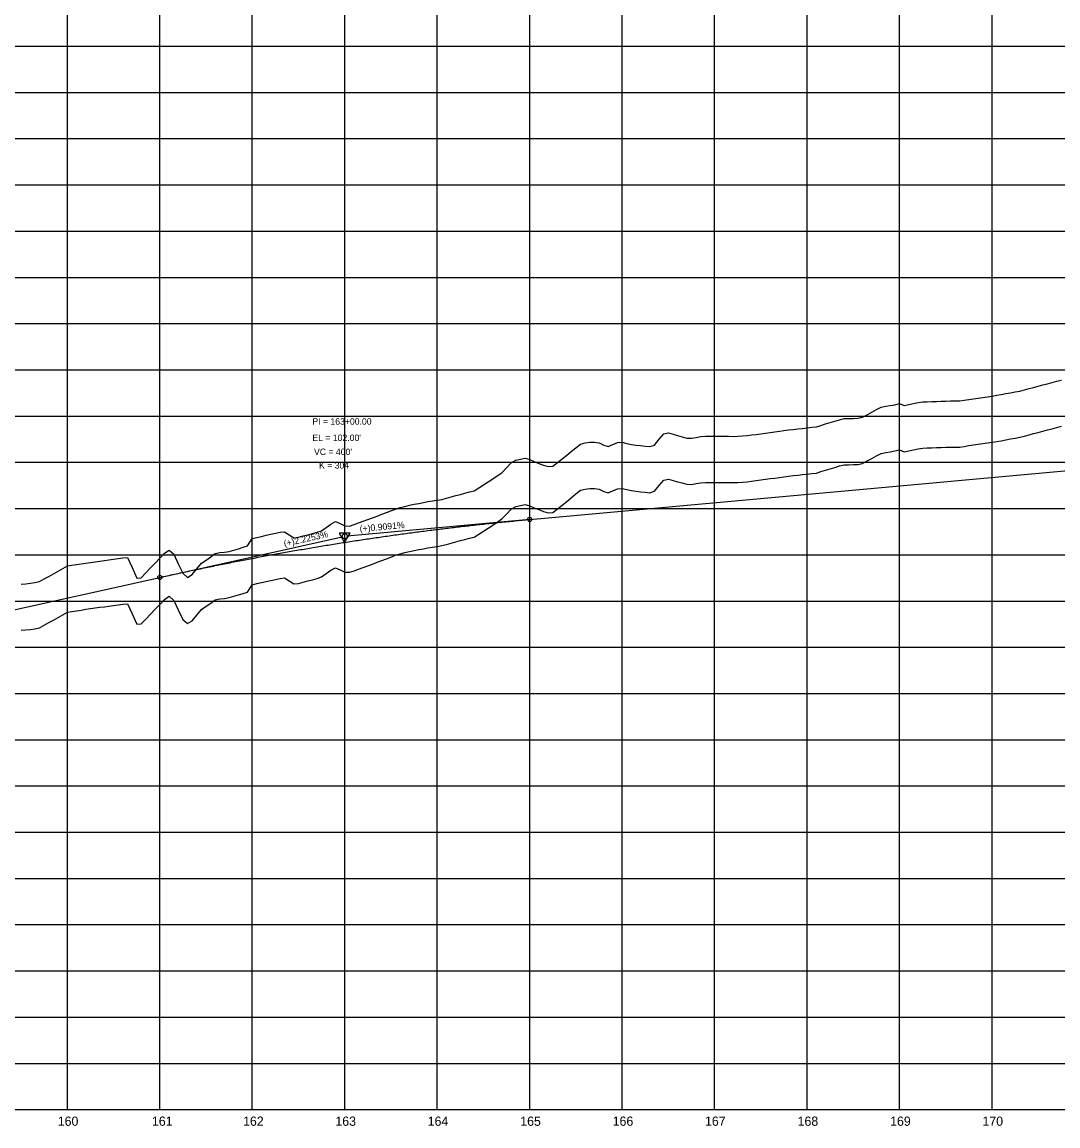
# Model space of a CAD drawing. Extents: x 2345490 to 2445302, y 465165 to 573888.
# Drawn here: x 2396273 to 2397393, y 564259 to 565453 of the extents above; entities that cross this region are included whole.
import ezdxf

# ---------------------------------------------------------------- set-up
doc = ezdxf.new("R2010")
doc.units = 0
for name, color, linetype in [('Old_Level_1', 7, 'Continuous'), ('Old_Level_2', 7, 'Continuous'), ('Old_Level_57', 7, 'Continuous'), ('Old_Level_62', 7, 'Continuous'), ('Old_Level_63', 7, 'Continuous')]:
    doc.layers.add(name, color=color, linetype=linetype)

msp = doc.modelspace()

# ---------------------------------------------------------------- linework, layer by layer
at = {"layer": 'Old_Level_1'}
for points in [[(2396871.5425, 564942.274), (2396876.5425, 564946.27125), (2396881.5425, 564947.5325), (2396886.5425, 564948.36975), (2396891.5425, 564948.22425), (2396896.5425, 564947.4575), (2396901.5425, 564944.9875), (2396906.5425, 564943.62775), (2396911.5425, 564945.76425), (2396916.5425, 564947.90375), (2396921.5425, 564948.2005), (2396926.5425, 564947.03125), (2396931.5425, 564945.8665), (2396936.5425, 564945.148), (2396941.5425, 564944.604), (2396946.5425, 564944.06375), (2396951.5425, 564943.52725), (2396956.5425, 564945.192), (2396961.5425, 564951.4745), (2396966.5425, 564957.15275), (2396971.5425, 564958.329), (2396976.5425, 564956.93625), (2396981.5425, 564955.54675), (2396986.5425, 564954.16075), (2396991.5425, 564952.77775), (2396996.5425, 564952.68825), (2397001.5425, 564953.484), (2397006.5425, 564954.28125), (2397011.5425, 564954.82525), (2397016.5425, 564954.83175), (2397021.5425, 564954.8395), (2397026.5425, 564954.84875), (2397031.5425, 564954.85925), (2397036.5425, 564954.80125), (2397041.5425, 564954.53975), (2397046.5425, 564954.86125), (2397051.5425, 564955.185), (2397056.5425, 564955.5105), (2397061.5425, 564956.0615), (2397066.5425, 564956.75125), (2397071.5425, 564957.4425), (2397076.5425, 564958.13575), (2397081.5425, 564958.83075), (2397086.5425, 564959.5275), (2397091.5425, 564960.22625), (2397096.5425, 564960.92675), (2397101.5425, 564961.62875), (2397106.5425, 564962.112), (2397111.5425, 564962.63875), (2397116.5425, 564963.2095), (2397121.5425, 564963.781), (2397126.5425, 564964.3535), (2397131.5425, 564964.93475), (2397136.5425, 564966.451), (2397141.5425, 564967.96875), (2397146.5425, 564969.488), (2397151.5425, 564971.009), (2397156.5425, 564972.53125), (2397161.5425, 564973.857), (2397166.5425, 564973.9555), (2397171.5425, 564974.06), (2397176.5425, 564974.16475), (2397181.5425, 564975.24425), (2397186.5425, 564977.9885), (2397191.5425, 564980.734), (2397196.5425, 564983.45175), (2397201.5425, 564986.16275), (2397206.5425, 564987.2385), (2397211.5425, 564988.02), (2397216.5425, 564988.80225), (2397221.5425, 564989.99125), (2397226.5425, 564987.83175), (2397231.5425, 564989.0185), (2397236.5425, 564990.06275), (2397241.5425, 564991.1085), (2397246.5425, 564991.86325), (2397251.5425, 564992.035), (2397256.5425, 564992.20725), (2397261.5425, 564992.3805), (2397266.5425, 564992.5545), (2397271.5425, 564992.729), (2397276.5425, 564992.84325), (2397281.5425, 564992.82825), (2397286.5425, 564993.04425), (2397291.5425, 564993.781), (2397296.5425, 564994.5185), (2397301.5425, 564995.25675), (2397306.5425, 564995.996), (2397311.5425, 564996.736), (2397316.5425, 564997.47675), (2397321.5425, 564998.21825), (2397326.5425, 564998.96075), (2397331.5425, 564999.87975), (2397336.5425, 565000.85575), (2397341.5425, 565001.79475), (2397346.5425, 565002.645), (2397351.5425, 565003.5365), (2397356.5425, 565004.8705), (2397361.5425, 565006.205), (2397366.5425, 565007.5405), (2397371.5425, 565008.8765)], [(2397371.5425, 565008.8765), (2397376.5425, 565010.2135), (2397381.5425, 565011.551), (2397386.5425, 565012.8895), (2397391.5425, 565014.2285), (2397396.5425, 565015.50025)], [(2396371.5425, 564821.8075), (2396376.5425, 564822.51275), (2396381.5425, 564823.21975), (2396386.5425, 564823.41025), (2396391.5425, 564812.7395), (2396396.5425, 564801.323), (2396401.5425, 564801.66625), (2396406.5425, 564806.9515), (2396411.5425, 564812.239), (2396416.5425, 564817.529), (2396421.5425, 564822.8215), (2396426.5425, 564828.11625), (2396431.5425, 564831.665), (2396436.5425, 564827.17725), (2396441.5425, 564816.8385), (2396446.5425, 564806.5055), (2396451.5425, 564802.0505), (2396456.5425, 564805.1195), (2396461.5425, 564811.28725), (2396466.5425, 564817.27225), (2396471.5425, 564820.7955), (2396476.5425, 564824.321), (2396481.5425, 564827.8485), (2396486.5425, 564828.9995), (2396491.5425, 564829.1725), (2396496.5425, 564830.183), (2396501.5425, 564831.64825), (2396506.5425, 564833.1215), (2396511.5425, 564834.60325), (2396516.5425, 564836.09325), (2396521.5425, 564844.14225), (2396526.5425, 564845.28575), (2396531.5425, 564846.429), (2396536.5425, 564847.5725), (2396541.5425, 564848.71625), (2396546.5425, 564849.85975), (2396551.5425, 564851.0035), (2396556.5425, 564851.4305), (2396561.5425, 564848.2085), (2396566.5425, 564844.995), (2396571.5425, 564845.5455), (2396576.5425, 564846.8515), (2396581.5425, 564848.16775), (2396586.5425, 564849.49425), (2396591.5425, 564850.8315), (2396596.5425, 564852.5395), (2396601.5425, 564856.1645), (2396606.5425, 564859.79125), (2396611.5425, 564862.40575), (2396616.5425, 564860.2005), (2396621.5425, 564857.8605), (2396626.5425, 564857.544), (2396631.5425, 564859.275), (2396636.5425, 564861.008), (2396641.5425, 564862.7425), (2396646.5425, 564864.60325), (2396651.5425, 564866.4955), (2396656.5425, 564868.38775), (2396661.5425, 564870.28), (2396666.5425, 564872.172), (2396671.5425, 564874.06425), (2396676.5425, 564875.95625), (2396681.5425, 564877.518), (2396686.5425, 564878.8225), (2396691.5425, 564880.0945), (2396696.5425, 564881.08325), (2396701.5425, 564882.071), (2396706.5425, 564883.05825), (2396711.5425, 564883.97175), (2396716.5425, 564884.78325), (2396721.5425, 564885.594), (2396726.5425, 564886.404), (2396731.5425, 564887.79625), (2396736.5425, 564889.23125), (2396741.5425, 564890.5355), (2396746.5425, 564891.838), (2396751.5425, 564893.13925), (2396756.5425, 564894.43875), (2396761.5425, 564895.737), (2396766.5425, 564898.93675), (2396771.5425, 564902.16525), (2396776.5425, 564905.4015), (2396781.5425, 564908.64525), (2396786.5425, 564911.89625), (2396791.5425, 564915.28525), (2396796.5425, 564920.54075), (2396801.5425, 564925.80425), (2396806.5425, 564928.726), (2396811.5425, 564929.896), (2396816.5425, 564931.039), (2396821.5425, 564929.57075), (2396826.5425, 564927.4465), (2396831.5425, 564925.3235), (2396836.5425, 564923.324), (2396841.5425, 564921.83175), (2396846.5425, 564922.3), (2396851.5425, 564926.29325), (2396856.5425, 564930.28725), (2396861.5425, 564934.282), (2396866.5425, 564938.2775), (2396871.5425, 564942.274)], [(2396271.5425, 564794.8795), (2396276.5425, 564795.2105), (2396281.5425, 564795.8615), (2396286.5425, 564796.5125), (2396291.5425, 564797.64525), (2396296.5425, 564800.418), (2396301.5425, 564803.191), (2396306.5425, 564805.9645), (2396311.5425, 564808.73825), (2396316.5425, 564811.5125), (2396321.5425, 564814.4905), (2396326.5425, 564815.312), (2396331.5425, 564816.05), (2396336.5425, 564816.7895), (2396341.5425, 564817.53), (2396346.5425, 564818.272), (2396351.5425, 564819.003), (2396356.5425, 564819.7015), (2396361.5425, 564820.402), (2396366.5425, 564821.10375), (2396371.5425, 564821.8075)]]:
    msp.add_lwpolyline(points, dxfattribs=at)
at = {"layer": 'Old_Level_2'}
for p, q in [((2396821.5425, 564914.71575), (2398621.5425, 565078.352)), ((2396821.5425, 564914.71575), (2396624.28125, 564896.78275)), ((2396421.5425, 564852.02725), (2396618.85825, 564895.9365)), ((2396221.5425, 564807.5205), (2396421.5425, 564852.02725))]:
    msp.add_line(p, q, dxfattribs=at)
msp.add_lwpolyline([(2396627.299, 564899.86625), (2396615.5565, 564899.85175), (2396621.44, 564889.7335)], close=True, dxfattribs=at)
for centre, radius in [((2396821.5425, 564914.71575), 2.25), ((2396621.5425, 564896.534), 2.75), ((2396421.5425, 564852.02725), 2.25)]:
    msp.add_circle(centre, radius, dxfattribs=at)
msp.add_spline([(2396421.5425, 564852.02725), (2396429.5425, 564853.797), (2396437.5425, 564855.5455), (2396445.5425, 564857.27325), (2396453.5425, 564858.97975), (2396461.5425, 564860.66525), (2396469.5425, 564862.32975), (2396477.5425, 564863.973), (2396485.5425, 564865.5955), (2396493.5425, 564867.19675), (2396501.5425, 564868.777), (2396509.5425, 564870.336), (2396517.5425, 564871.874), (2396525.5425, 564873.391), (2396533.5425, 564874.887), (2396541.5425, 564876.362), (2396549.5425, 564877.81575), (2396557.5425, 564879.2485), (2396565.5425, 564880.66025), (2396573.5425, 564882.051), (2396581.5425, 564883.4205), (2396589.5425, 564884.769), (2396597.5425, 564886.0965), (2396605.5425, 564887.403), (2396613.5425, 564888.68825), (2396621.5425, 564889.95275), (2396629.5425, 564891.196), (2396637.5425, 564892.418), (2396645.5425, 564893.61925), (2396653.5425, 564894.79925), (2396661.5425, 564895.95825), (2396669.5425, 564897.09625), (2396677.5425, 564898.213), (2396685.5425, 564899.309), (2396693.5425, 564900.38375), (2396701.5425, 564901.43725), (2396709.5425, 564902.47), (2396717.5425, 564903.4815), (2396725.5425, 564904.472), (2396733.5425, 564905.4415), (2396741.5425, 564906.39), (2396749.5425, 564907.31725), (2396757.5425, 564908.2235), (2396765.5425, 564909.10875), (2396773.5425, 564909.973), (2396781.5425, 564910.816), (2396789.5425, 564911.638), (2396797.5425, 564912.439), (2396805.5425, 564913.219), (2396813.5425, 564913.978), (2396821.5425, 564914.71575)], degree=3, dxfattribs=at)
at = {"layer": 'Old_Level_57'}
for p, q in [((2396321.5425, 564276.534), (2396321.5425, 566615.2835)), ((2396421.54225, 564276.534), (2396421.54225, 566615.2835)), ((2396521.54225, 564276.534), (2396521.54225, 566615.2835)), ((2396621.54225, 564276.534), (2396621.54225, 566615.2835)), ((2396721.54225, 564276.534), (2396721.54225, 566615.2835)), ((2396821.54225, 564276.534), (2396821.54225, 566615.2835)), ((2396921.54225, 564276.534), (2396921.54225, 566615.2835)), ((2397021.54225, 564276.534), (2397021.54225, 566615.2835)), ((2397121.54225, 564276.534), (2397121.54225, 566615.2835)), ((2397221.54225, 564276.534), (2397221.54225, 566615.2835)), ((2397321.5425, 564276.534), (2397321.5425, 566615.2835)), ((2381271.5425, 565426.534), (2410861.12275, 565426.534)), ((2381271.5425, 565376.534), (2410861.12275, 565376.534)), ((2381271.5425, 565326.534), (2410861.12275, 565326.534)), ((2381271.5425, 565276.534), (2410861.12275, 565276.534)), ((2381271.5425, 565226.534), (2410861.12275, 565226.534)), ((2381271.5425, 565176.534), (2410861.12275, 565176.534)), ((2381271.5425, 565126.534), (2410861.12275, 565126.534)), ((2381271.5425, 565076.534), (2410861.12275, 565076.534)), ((2381271.5425, 565026.534), (2410861.12275, 565026.534)), ((2381271.5425, 564976.534), (2410861.12275, 564976.534)), ((2381271.5425, 564926.534), (2410861.12275, 564926.534)), ((2381271.5425, 564876.534), (2410861.12275, 564876.534)), ((2381271.5425, 564826.534), (2410861.12275, 564826.534)), ((2381271.54275, 564776.534), (2410861.123, 564776.534)), ((2381271.5425, 564726.534), (2410861.12275, 564726.534)), ((2381271.54275, 564676.534), (2410861.123, 564676.534)), ((2381271.5425, 564626.534), (2410861.12275, 564626.534)), ((2381271.54275, 564576.534), (2410861.123, 564576.534)), ((2381271.5425, 564526.534), (2410861.12275, 564526.534)), ((2381271.54275, 564476.534), (2410861.123, 564476.534)), ((2381271.5425, 564426.534), (2410861.12275, 564426.534)), ((2381271.54275, 564376.534), (2410861.123, 564376.534)), ((2381271.5425, 564326.534), (2410861.12275, 564326.534)), ((2381271.54275, 564276.534), (2410861.123, 564276.534))]:
    msp.add_line(p, q, dxfattribs=at)
at = {"layer": 'Old_Level_63'}
msp.add_line((2381321.5425, 564276.534), (2406689.937, 564276.534), dxfattribs=at)
for points in [[(2396871.5425, 564992.27375), (2396876.5425, 564996.271), (2396881.5425, 564997.53225), (2396886.5425, 564998.3695), (2396891.5425, 564998.224), (2396896.5425, 564997.45725), (2396901.5425, 564994.98725), (2396906.5425, 564993.6275), (2396911.5425, 564995.764), (2396916.5425, 564997.9035), (2396921.5425, 564998.20025), (2396926.5425, 564997.031), (2396931.5425, 564995.86625), (2396936.5425, 564995.14775), (2396941.5425, 564994.60375), (2396946.5425, 564994.0635), (2396951.5425, 564993.527), (2396956.5425, 564995.19175), (2396961.5425, 565001.47425), (2396966.5425, 565007.1525), (2396971.5425, 565008.32875), (2396976.5425, 565006.936), (2396981.5425, 565005.5465), (2396986.5425, 565004.1605), (2396991.5425, 565002.7775), (2396996.5425, 565002.688), (2397001.5425, 565003.48375), (2397006.5425, 565004.281), (2397011.5425, 565004.825), (2397016.5425, 565004.8315), (2397021.5425, 565004.83925), (2397026.5425, 565004.8485), (2397031.5425, 565004.859), (2397036.5425, 565004.801), (2397041.5425, 565004.5395), (2397046.5425, 565004.861), (2397051.5425, 565005.18475), (2397056.5425, 565005.51025), (2397061.5425, 565006.06125), (2397066.5425, 565006.751), (2397071.5425, 565007.44225), (2397076.5425, 565008.1355), (2397081.5425, 565008.8305), (2397086.5425, 565009.52725), (2397091.5425, 565010.226), (2397096.5425, 565010.9265), (2397101.5425, 565011.6285), (2397106.5425, 565012.11175), (2397111.5425, 565012.6385), (2397116.5425, 565013.20925), (2397121.5425, 565013.78075), (2397126.5425, 565014.35325), (2397131.5425, 565014.9345), (2397136.5425, 565016.45075), (2397141.5425, 565017.9685), (2397146.5425, 565019.48775), (2397151.5425, 565021.00875), (2397156.5425, 565022.531), (2397161.5425, 565023.85675), (2397166.5425, 565023.95525), (2397171.5425, 565024.05975), (2397176.5425, 565024.1645), (2397181.5425, 565025.244), (2397186.5425, 565027.98825), (2397191.5425, 565030.73375), (2397196.5425, 565033.4515), (2397201.5425, 565036.1625), (2397206.5425, 565037.23825), (2397211.5425, 565038.01975), (2397216.5425, 565038.802), (2397221.5425, 565039.991), (2397226.5425, 565037.8315), (2397231.5425, 565039.01825), (2397236.5425, 565040.0625), (2397241.5425, 565041.10825), (2397246.5425, 565041.863), (2397251.5425, 565042.03475), (2397256.5425, 565042.207), (2397261.5425, 565042.38025), (2397266.5425, 565042.55425), (2397271.5425, 565042.72875), (2397276.5425, 565042.843), (2397281.5425, 565042.828), (2397286.5425, 565043.044), (2397291.5425, 565043.78075), (2397296.5425, 565044.51825), (2397301.5425, 565045.2565), (2397306.5425, 565045.99575), (2397311.5425, 565046.73575), (2397316.5425, 565047.4765), (2397321.5425, 565048.218), (2397326.5425, 565048.9605), (2397331.5425, 565049.8795), (2397336.5425, 565050.8555), (2397341.5425, 565051.7945), (2397346.5425, 565052.64475), (2397351.5425, 565053.53625), (2397356.5425, 565054.87025), (2397361.5425, 565056.20475), (2397366.5425, 565057.54025), (2397371.5425, 565058.87625)], [(2397371.5425, 565058.87625), (2397376.5425, 565060.21325), (2397381.5425, 565061.55075), (2397386.5425, 565062.88925), (2397391.5425, 565064.22825), (2397396.5425, 565065.5)], [(2396371.5425, 564871.80725), (2396376.5425, 564872.5125), (2396381.5425, 564873.2195), (2396386.5425, 564873.41), (2396391.5425, 564862.73925), (2396396.5425, 564851.32275), (2396401.5425, 564851.666), (2396406.5425, 564856.95125), (2396411.5425, 564862.23875), (2396416.5425, 564867.52875), (2396421.5425, 564872.82125), (2396426.5425, 564878.116), (2396431.5425, 564881.66475), (2396436.5425, 564877.177), (2396441.5425, 564866.83825), (2396446.5425, 564856.50525), (2396451.5425, 564852.05025), (2396456.5425, 564855.11925), (2396461.5425, 564861.287), (2396466.5425, 564867.272), (2396471.5425, 564870.79525), (2396476.5425, 564874.32075), (2396481.5425, 564877.84825), (2396486.5425, 564878.99925), (2396491.5425, 564879.17225), (2396496.5425, 564880.18275), (2396501.5425, 564881.648), (2396506.5425, 564883.12125), (2396511.5425, 564884.603), (2396516.5425, 564886.093), (2396521.5425, 564894.142), (2396526.5425, 564895.2855), (2396531.5425, 564896.42875), (2396536.5425, 564897.57225), (2396541.5425, 564898.716), (2396546.5425, 564899.8595), (2396551.5425, 564901.00325), (2396556.5425, 564901.43025), (2396561.5425, 564898.20825), (2396566.5425, 564894.99475), (2396571.5425, 564895.54525), (2396576.5425, 564896.85125), (2396581.5425, 564898.1675), (2396586.5425, 564899.494), (2396591.5425, 564900.83125), (2396596.5425, 564902.53925), (2396601.5425, 564906.16425), (2396606.5425, 564909.791), (2396611.5425, 564912.4055), (2396616.5425, 564910.20025), (2396621.5425, 564907.86025), (2396626.5425, 564907.54375), (2396631.5425, 564909.27475), (2396636.5425, 564911.00775), (2396641.5425, 564912.74225), (2396646.5425, 564914.603), (2396651.5425, 564916.49525), (2396656.5425, 564918.3875), (2396661.5425, 564920.27975), (2396666.5425, 564922.17175), (2396671.5425, 564924.064), (2396676.5425, 564925.956), (2396681.5425, 564927.51775), (2396686.5425, 564928.82225), (2396691.5425, 564930.09425), (2396696.5425, 564931.083), (2396701.5425, 564932.07075), (2396706.5425, 564933.058), (2396711.5425, 564933.9715), (2396716.5425, 564934.783), (2396721.5425, 564935.59375), (2396726.5425, 564936.40375), (2396731.5425, 564937.796), (2396736.5425, 564939.231), (2396741.5425, 564940.53525), (2396746.5425, 564941.83775), (2396751.5425, 564943.139), (2396756.5425, 564944.4385), (2396761.5425, 564945.73675), (2396766.5425, 564948.9365), (2396771.5425, 564952.165), (2396776.5425, 564955.40125), (2396781.5425, 564958.645), (2396786.5425, 564961.896), (2396791.5425, 564965.285), (2396796.5425, 564970.5405), (2396801.5425, 564975.804), (2396806.5425, 564978.72575), (2396811.5425, 564979.89575), (2396816.5425, 564981.03875), (2396821.5425, 564979.5705), (2396826.5425, 564977.44625), (2396831.5425, 564975.32325), (2396836.5425, 564973.32375), (2396841.5425, 564971.8315), (2396846.5425, 564972.29975), (2396851.5425, 564976.293), (2396856.5425, 564980.287), (2396861.5425, 564984.28175), (2396866.5425, 564988.27725), (2396871.5425, 564992.27375)], [(2396271.5425, 564844.87925), (2396276.5425, 564845.21025), (2396281.5425, 564845.86125), (2396286.5425, 564846.51225), (2396291.5425, 564847.645), (2396296.5425, 564850.41775), (2396301.5425, 564853.19075), (2396306.5425, 564855.96425), (2396311.5425, 564858.738), (2396316.5425, 564861.51225), (2396321.5425, 564864.49025), (2396326.5425, 564865.31175), (2396331.5425, 564866.04975), (2396336.5425, 564866.78925), (2396341.5425, 564867.52975), (2396346.5425, 564868.27175), (2396351.5425, 564869.00275), (2396356.5425, 564869.70125), (2396361.5425, 564870.40175), (2396366.5425, 564871.1035), (2396371.5425, 564871.80725)]]:
    msp.add_lwpolyline(points, dxfattribs=at)

# ---------------------------------------------------------------- texts
at = {"layer": 'Old_Level_2'}
for s, height, p in [('PI = 163+00.00', 7.0000005, (2396586.54275, 565017.2145)), ("EL = 102.00'", 7.0000005, (2396586.5425, 564999.534)), ("VC = 400'", 7.000001, (2396588.3075, 564984.35075)), ('K = 304', 7.000001, (2396593.718, 564969.7455))]:
    msp.add_text(s, height=height, dxfattribs=at).set_placement(p)
for s, rotation, p in [('(+)0.9091%', 5.19442778, (2396638.00175, 564901.04225)), ('(+)2.2253%', 12.54579444, (2396556.45625, 564885.12325))]:
    msp.add_text(s, height=7.000001, rotation=rotation, dxfattribs=at).set_placement(p)
at = {"layer": 'Old_Level_62'}
for s, p in [('160', (2396311.1715, 564259.034)), ('161', (2396413.01075, 564259.034)), ('162', (2396511.55925, 564259.034)), ('163', (2396611.394, 564259.034)), ('164', (2396711.2365, 564259.034)), ('165', (2396811.329, 564259.034)), ('166', (2396911.27, 564259.034)), ('167', (2397011.1275, 564259.034)), ('168', (2397111.25325, 564259.034)), ('169', (2397211.2955, 564259.034)), ('170', (2397311.1715, 564259.034))]:
    msp.add_text(s, height=10.000001, dxfattribs=at).set_placement(p)

doc.saveas('drawing.dxf')
